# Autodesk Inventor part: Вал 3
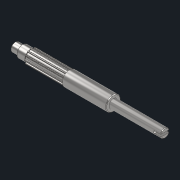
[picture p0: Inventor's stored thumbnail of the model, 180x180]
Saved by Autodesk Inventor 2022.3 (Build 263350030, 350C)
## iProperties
Created: 2022-08
Part Number: Вал 3
Material: Сталь 40ХНМА
Document SubType Name: Modeling
Designer: Карташов
Density: 7.85 g/cm^3
Appearance: С умеренной полировкой
Author: Карташов
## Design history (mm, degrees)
sketch "Эскиз1"
  geometry: L1 (0, 0)-(-510.59, 0); L2 (0, 0)-(0, 15); L3 (0, 15)-(-175.59, 15); L4 (-175.59, 15)-(-175.59, 25); L5 (-175.59, 25)-(-324.59, 25); L6 (-324.59, 25)-(-324.59, 27.5); L7 (-324.59, 27.5)-(-454.59, 27.5); L8 (-454.59, 27.5)-(-454.59, 18.75); L9 (-457.09, 18.75)-(-457.09, 20); L10 (-457.09, 20)-(-484.59, 20); L11 (-484.59, 20)-(-484.59, 15); L12 (-484.59, 15)-(-510.59, 15); L13 (-510.59, 15)-(-510.59, 0); L14 (-457.09, 18.75)-(-454.59, 18.75); 1 further point
  constraints: 28 end point, 5 perpendicular, 4 horizontal, 3 parallel, 2 vertical, 1 midpoint
  dimensions: "d0" = 30 diameter of L3 L1; "d1" = 50 diameter of L5 L1; "d2" = 55 diameter of L7 L1; "d3" = 40 diameter of L10 L1; "d4" = 30 diameter of L12 L1; "d5" = 37.5 diameter of L14 L1; "d6" = 26 distance of L11.end L12.end; "d7" = 30 distance from line of L8 point (-484.59, 17.5); "d8" = 2.5 distance of L9.start L8.end; "d9" = 130 distance of L6.end L7.end; "d10" = 149 distance of L4.end L5.end; "d11" = 175.59 distance of L2.end L3.end
revolve "Вращение1" sketch "Эскиз1" stored, may be unused: angle "d12" = 90 deg
chamfer "Фаска1" distance "d13" = 2; stored, may be unused: second distance "d14" = 2, angle "d15" = 45 deg
chamfer "Фаска2" distance "d16" = 1; stored, may be unused: second distance "d17" = 2, angle "d18" = 45 deg
sketch "Эскиз2"
  geometry: L1 (-2, 19.9)-(-2, 23); L2 (-1, 24)-(1, 24); L3 (2, 23)-(2, 19.9); C1 r 18.75 at (0, 0) reference; C2 r 27.5 at (0, 0) reference; C3 r 20 at (0, 0); A1 r 20 centre (0, 0) between (-2, 19.9) and (2, 19.9) reference; A2 r 1 centre (-1, 23) between (-1, 24) and (-2, 23); A3 r 1 centre (1, 23) between (2, 23) and (1, 24); 6 further points
  constraints: 6 end point, 6 point on circle, 4 point on line, 4 tangent, 3 centre point, 2 vertical, 1 coincident, 1 equal radius, 1 horizontal, 1 midpoint, 1 vertical alignment
  dimensions: "d19" = 40 diameter of C3; "d20" = 24 distance from line of C2.centre L2; "d21" = 4 distance of point (-2, 24) point (2, 24); "d22" = 1 radius of A2
  node "Спроецированная петля1"
extrude "Выдавливание1" cut sketch "Эскиз2" distance "d23" = 130; taper "d24" = 0 deg
extrude "Выдавливание2" join sketch "Эскиз2" distance "d25" = 130; taper "d26" = 0 deg
pattern_circular "Круговой массив1" dims angle "d28" = 360 deg
sketch "Эскиз3"
  geometry: L1 (0, 13)-(0, -13) reference; L2 (0, 4)-(-21, 4); L3 (-21, 4)-(-21, -4); L4 (-21, -4)-(0, -4); L5 (0, -4)-(0, 4); A1 r 4 centre (-21, 0) between (-21, 4) and (-21, -4); 4 further points
  constraints: 8 end point, 2 midpoint, 2 parallel, 2 point on circle, 2 tangent, 1 centre point, 1 horizontal, 1 horizontal alignment, 1 perpendicular, 1 point on line
  dimensions: "d30" = 4 radius of A1; "d31" = 21 distance of L2.start L2.end
extrude "Выдавливание3" cut sketch "Эскиз3" extent not by distance; stored distance "d32" = 0; taper "d33" = 0 deg
node "Твердое тело1"
